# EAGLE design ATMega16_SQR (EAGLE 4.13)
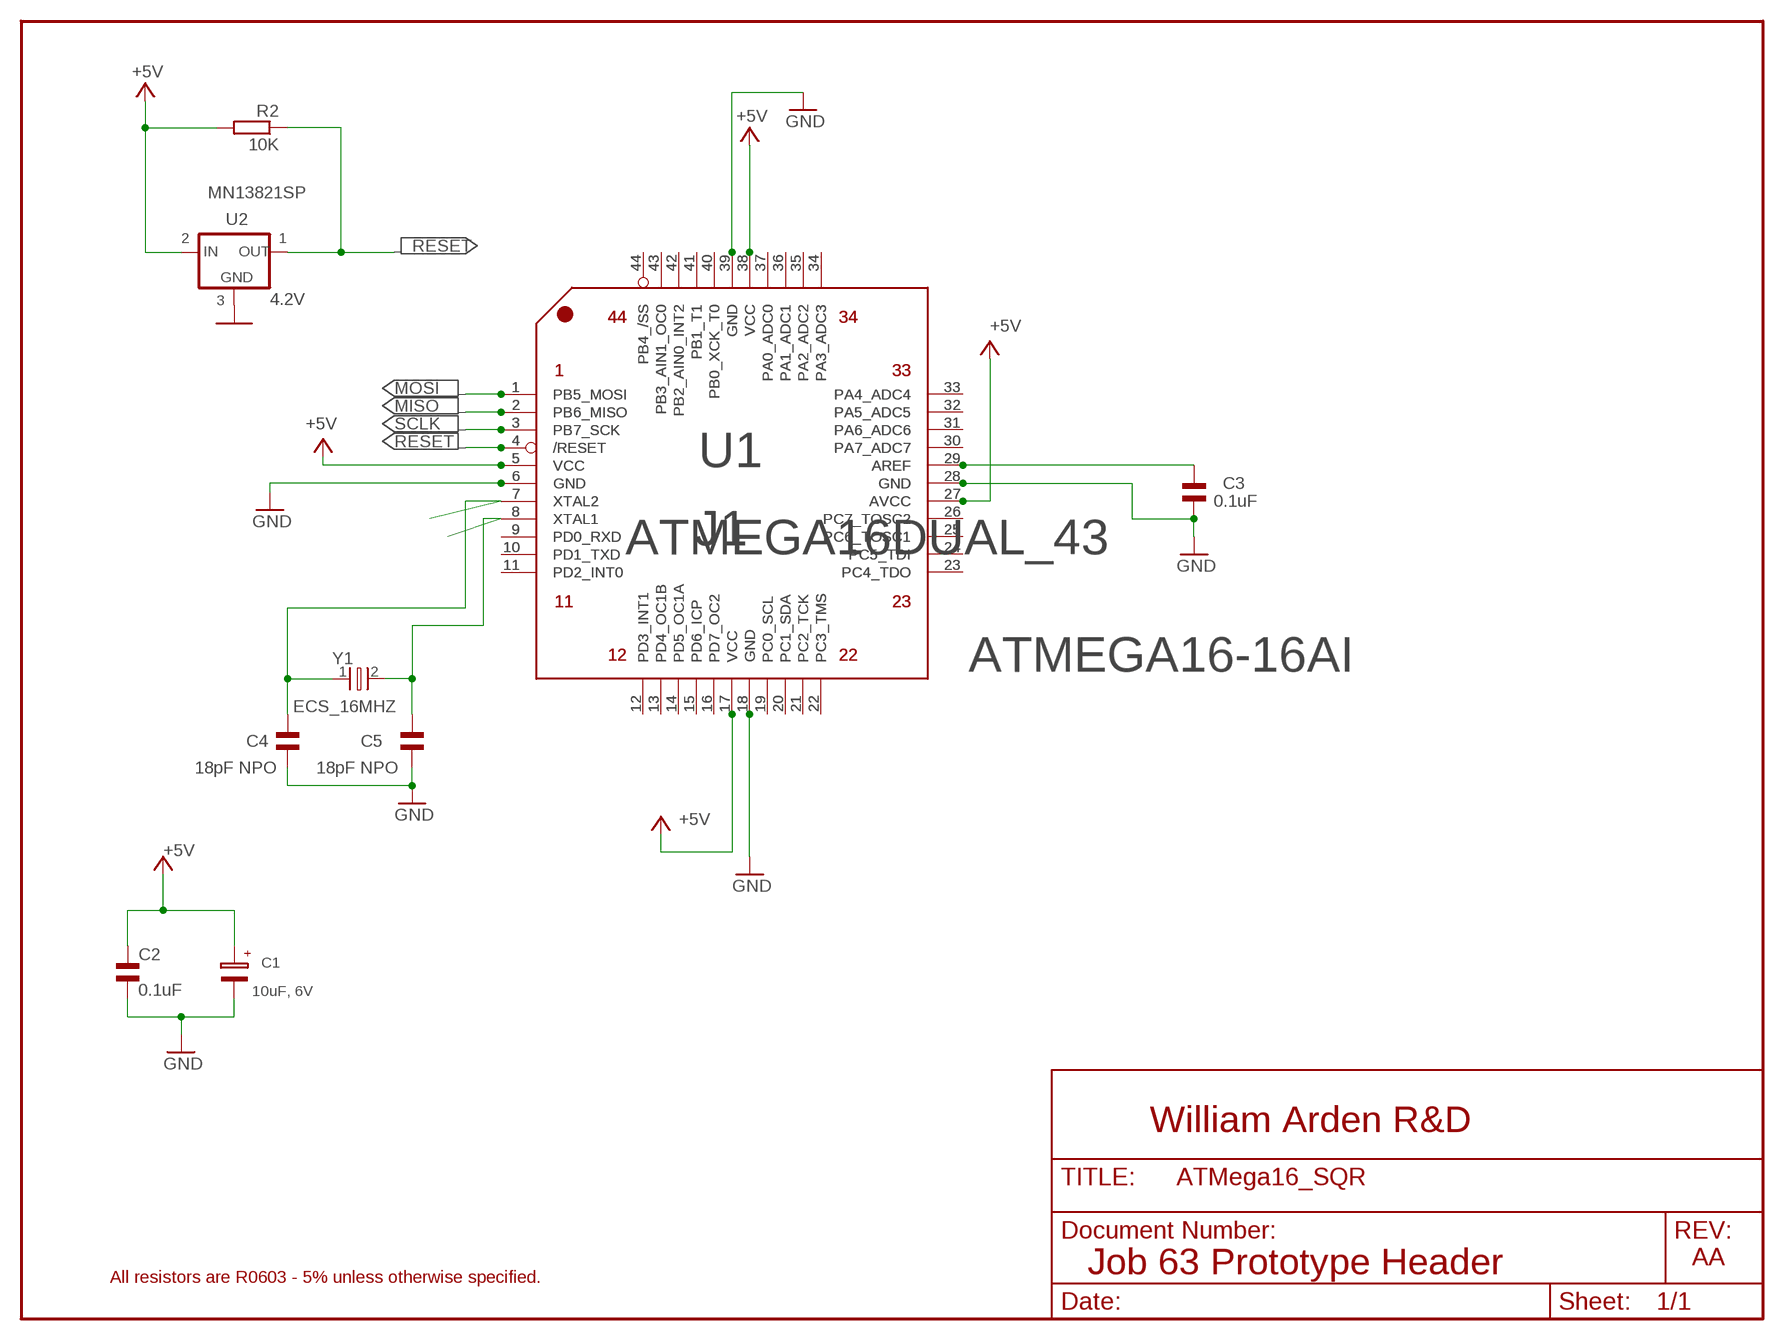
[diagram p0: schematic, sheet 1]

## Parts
C1  10uF, 6V  CAP_TANT_SIZE_A  [CAP_SIZE_A]
C2  0.1uF  C0603  [C0603]
C3  0.1uF  C0603  [C0603]
C4  18pF NPO  C0603  [C0603]
C5  18pF NPO  C0603  [C0603]
J1  ATMEGA16DUAL_43  [HEADER_DUALSQR44_43]
R2  10K  R0603  [R0603]
U1  ATMEGA16-16AI  [TQFP-44]
U2  MN13821SP  MN13821SP_BIGGER_PADS  [MINITYPE_BIGGER_PADS]
Y1  ECS_16MHZ  XTALECS_8MHZ  [XTAL-ECS]

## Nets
+5V: C1.+ C2.2 J1.5(VCC) J1.17(VCC) J1.27(AVCC) J1.38(VCC) R2.2 U1.5(VCC) U1.17(VCC) U1.27(AVCC) U1.38(VCC) U2.2(IN)
ADC0: J1.37(PA0_ADC0) U1.37(PA0_ADC0)
ADC1: J1.36(PA1_ADC1) U1.36(PA1_ADC1)
ADC2: J1.35(PA2_ADC2) U1.35(PA2_ADC2)
ADC3: J1.34(PA3_ADC3) U1.34(PA3_ADC3)
ADC6: J1.31(PA6_ADC6) U1.31(PA6_ADC6)
ADC7: J1.30(PA7_ADC7) U1.30(PA7_ADC7)
AIN0: J1.42(PB2_AIN0_INT2) U1.42(PB2_AIN0_INT2)
AIN1: J1.43(PB3_AIN1_OC0) U1.43(PB3_AIN1_OC0)
GND: C1.- C2.1 C3.1 C4.1 C5.1 J1.6(GND) J1.18(GND) J1.28(GND) J1.39(GND) U1.6(GND) U1.18(GND) U1.28(GND) U1.39(GND) U2.3(GND)
INT0: J1.11(PD2_INT0) U1.11(PD2_INT0)
INT1: J1.12(PD3_INT1) U1.12(PD3_INT1)
LED2: J1.40(PB0_XCK_T0) U1.40(PB0_XCK_T0)
MISO: J1.2(PB6_MISO) U1.2(PB6_MISO)
MOSI: J1.1(PB5_MOSI) U1.1(PB5_MOSI)
N$1: J1.15(PD6_ICP) U1.15(PD6_ICP)
N$2: J1.16(PD7_OC2) U1.16(PD7_OC2)
N$19: C3.2 J1.29(AREF) U1.29(AREF)
NETIN: J1.14(PD5_OC1A) U1.14(PD5_OC1A)
NOTUSED1: J1.7(XTAL2)
NOTUSED2: J1.8(XTAL1)
OC1B: J1.13(PD4_OC1B) U1.13(PD4_OC1B)
PC0: J1.19(PC0_SCL) U1.19(PC0_SCL)
PC1: J1.20(PC1_SDA) U1.20(PC1_SDA)
PC2: J1.21(PC2_TCK) U1.21(PC2_TCK)
PC3: J1.22(PC3_TMS) U1.22(PC3_TMS)
PC4: J1.23(PC4_TDO) U1.23(PC4_TDO)
PC5: J1.24(PC5_TDI) U1.24(PC5_TDI)
PC6: J1.25(PC6_TOSC1) U1.25(PC6_TOSC1)
PC7: J1.26(PC7_TOSC2) U1.26(PC7_TOSC2)
PD0RX: J1.9(PD0_RXD) U1.9(PD0_RXD)
PD1TX: J1.10(PD1_TXD) U1.10(PD1_TXD)
RESET: J1.4(/RESET) R2.1 U1.4(/RESET) U2.1(OUT)
SCLK: J1.3(PB7_SCK) U1.3(PB7_SCK)
SS: J1.44(PB4_/SS) U1.44(PB4_/SS)
T1: J1.41(PB1_T1) U1.41(PB1_T1)
XTAL1: C5.2 U1.8(XTAL1) Y1.2
XTAL2: C4.2 U1.7(XTAL2) Y1.1
YSIG: J1.33(PA4_ADC4) U1.33(PA4_ADC4)
ZSIG: J1.32(PA5_ADC5) U1.32(PA5_ADC5)

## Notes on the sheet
- 4.2V
- William Arden R&D
- AA
- Job 63 Prototype Header
- All resistors are R0603 - 5% unless otherwise specified.

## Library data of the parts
C1 = 0_Darren:CAP_TANT: Capacitor, Tantalum
C2-C5 = ipc-rcl:C0603
J1 U1 = Atmel_Prototype_Header:ATMEGA16: 8-bit AVR Microcontroller with 16K Bytes In-System Programmable Flash
R2 = ipc-rcl:R0603
U2 = 0_Darren:MN13821SP: IC VOLT DETECT 4.2V N-CH OD SMD
Y1 = 0_Darren:XTAL: CRYSTAL 8.00MHZ 18PF SMD , Example: ECS, Inc. Part # ECS-80-18-5P-TR

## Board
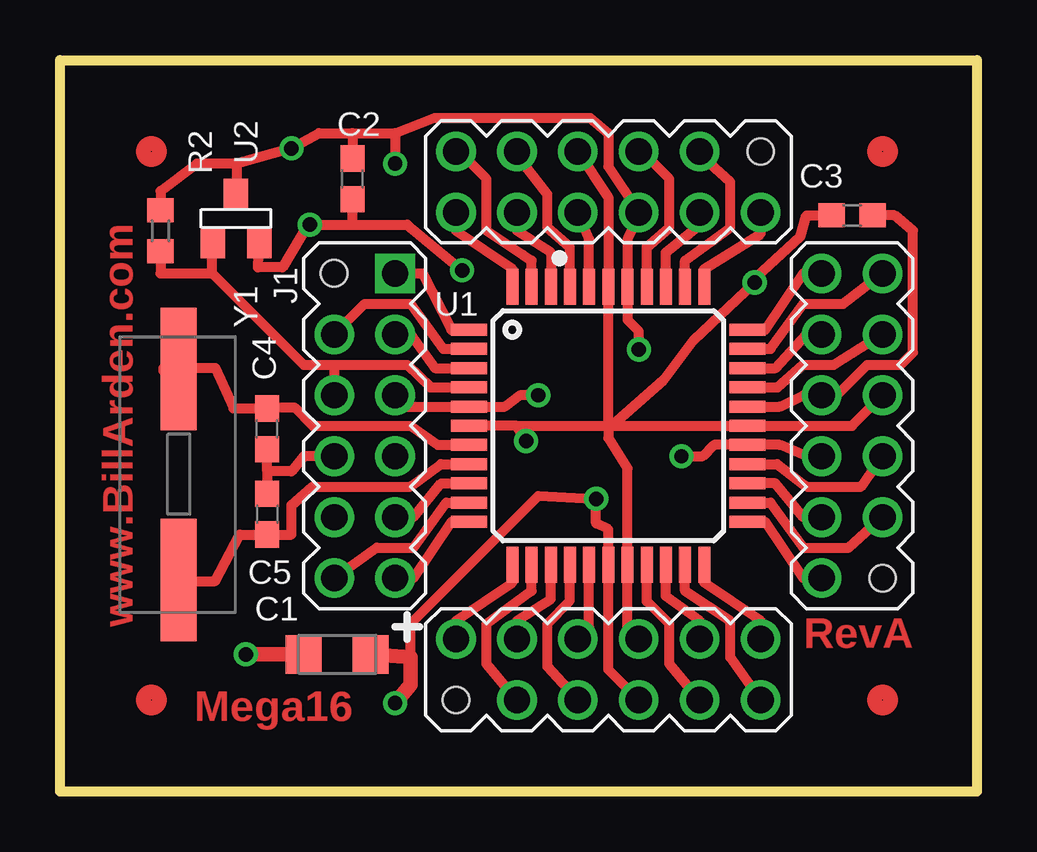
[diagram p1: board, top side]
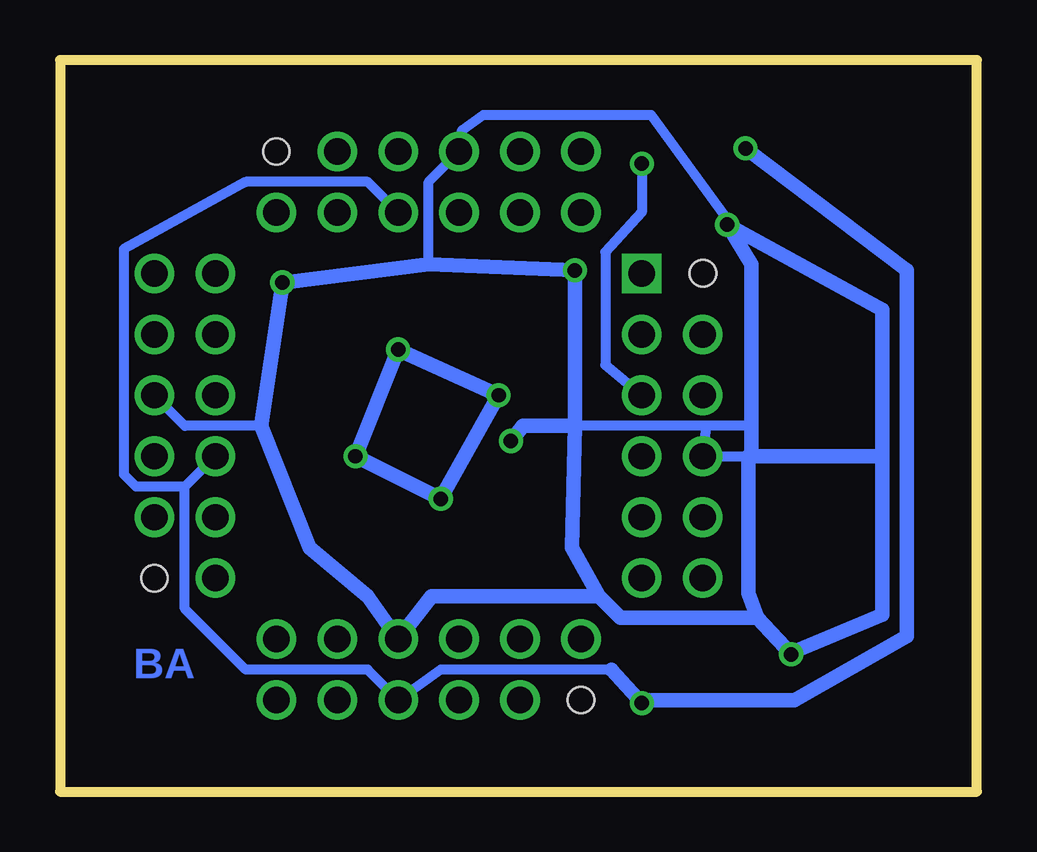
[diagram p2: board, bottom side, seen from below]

Size 38.23 x 30.48 mm. Coordinates in mm from the lower left corner, seen from the top.
Outline: 38.23,30.48 38.23,0 0,0 0,30.48 38.23,30.48
Copper layers (1*16): Top 0.035mm / dielectric 0.5mm / Bottom 0.035mm
Design rules "RestringMinZero": minimum track width 6mil, minimum drill 12mil, track to track 8mil, track to pad 8mil, pad to pad 8mil, via to via 8mil, smd to smd 8mil, copper to edge 0mil, drill to drill 8mil, minimum pad ring 0mil, minimum via ring 8mil, stop-mask expansion 0mil, vias tented up to drill 20mil, thermal gap 12mil
tRestrict: 4 lines

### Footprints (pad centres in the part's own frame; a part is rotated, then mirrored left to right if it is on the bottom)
CAP_SIZE_A = smd 1.5 x 1.6: + -1.4,0; - 1.4,0
C0603 = smd 1.1 x 1: 1 -0.85,0; 2 0.85,0
HEADER_DUALSQR44_43 = drill 1.1 square: 1 -8.89,6.35 | drill 1.1 round: 2 -11.43,3.81; 3 -8.89,3.81; 4 -11.43,1.27; 5 -8.89,1.27; 6 -11.43,-1.27; 7 -8.89,-1.27; 8 -11.43,-3.81; 9 -8.89,-3.81; 10 -11.43,-6.35; 11 -8.89,-6.35; 12 -6.35,-8.89; 13 -3.81,-11.43; 14 -3.81,-8.89; 15 -1.27,-11.43; 16 -1.27,-8.89; 17 1.27,-11.43; 18 1.27,-8.89; 19 3.81,-11.43; 20 3.81,-8.89; 21 6.35,-11.43; 22 6.35,-8.89; 23 8.89,-6.35; 24 11.43,-3.81; 25 8.89,-3.81; 26 11.43,-1.27; 27 8.89,-1.27; 28 11.43,1.27; 29 8.89,1.27; 30 11.43,3.81; 31 8.89,3.81; 32 11.43,6.35; 33 8.89,6.35; 34 6.35,8.89; 35 3.81,11.43; 36 3.81,8.89; 37 1.27,11.43; 38 1.27,8.89; 39 -1.27,11.43; 40 -1.27,8.89; 41 -3.81,11.43; 42 -3.81,8.89; 43 -6.35,11.43; 44 -6.35,8.89 | hole 1.1: -11.43,6.35; -6.35,-11.43; 11.43,-6.35; 6.35,11.43
R0603 = smd 1 x 1.1: 1 -0.85,0; 2 0.85,0
TQFP-44 = smd 1.5 x 0.5: 1 -5.8,4; 2 -5.8,3.2; 3 -5.8,2.4; 4 -5.8,1.6; 5 -5.8,0.8; 6 -5.8,0; 7 -5.8,-0.8; 8 -5.8,-1.6; 9 -5.8,-2.4; 10 -5.8,-3.2; 11 -5.8,-4; 23 5.8,-4; 24 5.8,-3.2; 25 5.8,-2.4; 26 5.8,-1.6; 27 5.8,-0.8; 28 5.8,0; 29 5.8,0.8; 30 5.8,1.6; 31 5.8,2.4; 32 5.8,3.2; 33 5.8,4 | smd 0.5 x 1.5: 12 -4,-5.8; 13 -3.2,-5.8; 14 -2.4,-5.8; 15 -1.6,-5.8; 16 -0.8,-5.8; 17 0,-5.8; 18 0.8,-5.8; 19 1.6,-5.8; 20 2.4,-5.8; 21 3.2,-5.8; 22 4,-5.8; 34 4,5.8; 35 3.2,5.8; 36 2.4,5.8; 37 1.6,5.8; 38 0.8,5.8; 39 0,5.8; 40 -0.8,5.8; 41 -1.6,5.8; 42 -2.4,5.8; 43 -3.2,5.8; 44 -4,5.8
MINITYPE_BIGGER_PADS = smd 1.016 x 1.27: 1 0.991,1.016; 2 0.025,-1.016; 3 -0.94,1.016
XTAL-ECS = smd 5.1 x 1.5: 1 -4.4,0; 2 4.4,0

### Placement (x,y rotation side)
C1  11.56,5.71 180 top
C2  12.19,25.53 90 top
C3  33.02,24 0 top
C4  8.64,15.11 90 top
C5  8.64,11.56 270 top
J1  22.86,15.24 0 top
R2  4.19,23.37 90 top
U1  22.86,15.24 0 top
U2  7.37,23.88 180 top
U$1  [DRAWING]  not placed on the board
U$2  [FIDUCIAL]  3.81,3.81 0 top
U$3  [FIDUCIAL]  34.29,3.81 0 top
U$4  [FIDUCIAL]  34.29,26.67 0 top
U$10  [FIDUCIAL]  3.81,26.67 270 top
Y1  4.95,13.21 270 top

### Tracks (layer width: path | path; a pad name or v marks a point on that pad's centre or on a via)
+5V  (via drill 0.6)
  Top 0.406: J1.5 14.44,16.04 U1.5 18.54,16.04 19.18,16.51 v19.94,16.51 | J1.27 31.11,13.97 30.01,14.44 U1.27 27.27,14.44 26.8,13.97 v25.91,13.97 | J1.17 22.86,5.08 U1.17 22.86,10.92 22.35,11.18 v22.35,12.19 | R2.2 4.19,25.02 5.71,26.16 7.37,26.16 | U2.2 7.37,25.65 7.37,26.16 | v24.13,18.41 24.13,19.18 23.66,19.65 U1.38 23.66,23.02 24.13,24 J1.38 22.86,26.04 22.86,27.43 22.1,28.07 15.62,28.07 13.97,27.43 | 12.19,27.43 C2.2 | 13.97,27.43 v13.97,26.16 | 7.37,26.16 v9.65,26.8 10.79,27.43 12.19,27.43 | 12.19,27.43 13.97,27.43 | 14.61,5.59 14.61,6.99 19.94,12.32 22.23,12.19
  Top 0.61: v9.65,26.8 9.53,26.8 | v13.97,3.68 14.61,4.45 14.61,5.59 C1.+
  Bottom 0.406: 15.24,5.08 22.35,5.08 J1.17 25.4,5.08 30.48,5.08 33.02,7.62 33.02,12.7 | v13.97,26.16 13.97,24.13 15.49,22.48 15.49,17.78 J1.5 | 33.02,12.7 35.05,12.7 35.56,13.21 35.56,22.61 30.48,25.4 25.4,25.4 J1.38 | 33.02,12.7 J1.27 | 13.97,3.81 v13.97,3.68
  Bottom 0.61: v13.97,3.68 15.24,5.08 | 13.97,3.81 7.62,3.81 2.92,6.48 2.92,21.72 v9.65,26.8 | v19.94,16.51 v24.13,18.41 v25.91,13.97 v22.35,12.19 v19.94,16.51
ADC0
  Top 0.406: U1.37 24.46,22.68 25.4,23.5 25.4,25.53 24.26,26.67 J1.37
ADC1
  Top 0.406: U1.36 25.26,22.47 26.67,23.62 J1.36
ADC2
  Top 0.406: U1.35 26.06,22.12 27.94,23.5 27.94,25.4 26.67,26.54 J1.35
ADC3
  Top 0.406: U1.34 26.86,21.78 29.21,23.24 J1.34
ADC6
  Top 0.406: U1.31 29.83,17.64 31.11,19.05 J1.31
ADC7
  Top 0.406: U1.30 29.92,16.84 30.99,17.78 32.26,17.78 J1.30
AIN0
  Top 0.406: U1.42 20.46,22.47 19.05,23.37 J1.42
AIN1
  Top 0.406: U1.43 19.66,22.12 19.3,22.35 17.78,23.37 17.78,25.53 16.51,26.8 J1.43
GND  (via drill 0.6)
  Top 0.406: 22.86,21.59 U1.39 | 22.86,21.59 22.86,24.77 J1.39 | J1.28 33.02,15.24 U1.28 22.86,15.24 | J1.18 23.66,6.82 U1.18 23.66,13.46 22.86,14.73 22.86,15.11 | 22.86,15.11 22.86,21.59 | 19.05,15.24 22.86,15.24 | 22.86,15.24 22.86,15.11 | 8.64,13.34 C4.1 | 8.64,13.34 9.65,13.34 10.16,13.97 J1.6 | 8.64,13.34 C5.1 | U2.3 8.26,21.84 9.27,21.84 10.41,23.75 v10.41,23.62 12.19,23.62 | 19.05,15.24 U1.6 | v19.43,14.61 19.05,15.24 | C3.1 31.11,24 30.86,23.11 29.08,21.46 29.21,21.59 v28.96,21.21 26.42,18.8 25.15,17.14 22.86,15.11 | v16.76,21.72 14.48,23.62 12.19,23.62 | 12.19,23.62 C2.1
  Top 0.61: v7.75,5.71 C1.-
  Bottom 0.406: 9.53,13.97 J1.6 11.3,15.24 | 11.3,15.24 16.76,15.24 | 9.4,15.24 11.3,15.24 | 10.16,23.5 13.59,28.19 20.57,28.19 21.46,27.56 J1.39 22.86,25.4 22.86,21.97 | 29.84,15.24 33.02,15.24 J1.28
  Bottom 0.61: 9.53,13.97 9.53,8.26 9.14,7.24 | v19.43,14.61 18.92,15.24 16.76,15.24 | 7.87,5.71 3.94,7.37 3.94,13.97 | 3.94,13.97 3.94,20.07 v10.41,23.62 9.4,21.97 9.4,15.24 9.4,13.97 3.94,13.97 | 9.14,7.24 v7.75,5.71 | 9.14,7.24 14.86,7.24 15.75,8.13 | 15.75,8.13 16.89,10.16 16.76,15.24 | 15.75,8.13 22.73,8.13 J1.18 25.4,8.13 27.81,10.16 29.84,15.24 v28.96,21.21 22.86,21.97 v16.76,21.72 16.76,15.24
INT0
  Top 0.406: U1.11 16.32,11.24 14.73,8.89 J1.11
INT1
  Top 0.406: U1.12 18.86,8.7 16.51,7.11 J1.12
LED2
  Top 0.406: U1.40 22.06,23.02 J1.40
MISO
  Top 0.406: U1.2 15.98,18.44 14.61,20.32 12.7,20.32 J1.2
MOSI
  Top 0.406: U1.1 16.32,19.24 15.11,21.59 J1.1
N$1
  Top 0.406: U1.15 21.26,7.95 20.32,6.99 20.32,5.21 J1.15
N$2
  Top 0.406: U1.16 22.06,6.82 J1.16
N$19
  Top 0.406: U1.29 30.01,16.04 30.99,16.51 J1.29 32.38,16.51 33.66,17.78 35.05,17.78 35.56,18.29 35.56,23.37 34.8,24 C3.2
NETIN
  Top 0.406: U1.14 20.46,8.01 19.05,7.11 J1.14
OC1B
  Top 0.406: U1.13 19.66,8.36 17.78,6.99 17.78,5.33 J1.13
PC0
  Top 0.406: U1.19 24.46,7.92 25.4,6.99 25.4,5.33 J1.19
PC1
  Top 0.406: U1.20 25.26,8.14 26.67,7.11 J1.20
PC2
  Top 0.406: U1.21 26.06,8.36 27.94,7.11 27.94,5.59 J1.21
PC3
  Top 0.406: U1.22 26.86,8.7 29.21,7.11 J1.22
PC4
  Top 0.406: U1.23 29.4,11.24 30.99,8.89 J1.23
PC5
  Top 0.406: U1.24 29.62,12.04 30.99,10.16 32.89,10.16 J1.24
PC6
  Top 0.406: U1.25 29.83,12.84 30.99,11.43 J1.25
PC7
  Top 0.406: U1.26 29.9,13.64 31.11,12.7 33.4,12.7 J1.26
PD0RX
  Top 0.406: U1.9 15.89,12.84 14.73,11.43 J1.9
PD1TX
  Top 0.406: U1.10 16.1,12.04 14.73,10.16 13.21,10.16 J1.10
RESET
  Top 0.406: U1.4 15.44,16.84 14.48,17.78 11.43,17.78 | 11.43,17.78 J1.4 | 11.43,17.78 10.16,17.78 6.35,21.59 | U2.1 6.35,22.48 6.35,21.59 | 6.35,21.59 4.19,21.59 R2.1
SCLK
  Top 0.406: U1.3 15.63,17.64 14.61,19.05 J1.3
SS
  Top 0.406: U1.44 18.86,21.78 16.51,23.37 J1.44
T1
  Top 0.406: U1.41 21.26,22.68 20.32,23.5 20.32,24.89 18.92,26.67 J1.41
XTAL1
  Top 0.406: U1.8 15.88,13.64 14.61,12.7 10.54,12.7 9.65,11.94 9.65,10.71 C5.2 7.49,10.71 6.48,8.76 4.45,8.76 4.45,8.81 Y1.2
XTAL2
  Top 0.406: U1.7 15.75,14.44 14.61,15.24 10.54,15.24 9.78,16 8.89,16 C4.2 7.24,15.96 6.48,17.65 4.32,17.65 Y1.1 4.32,17.53
YSIG
  Top 0.406: U1.33 29.4,19.24 30.99,21.59 J1.33
ZSIG
  Top 0.406: U1.32 29.62,18.44 30.99,20.32 32.64,20.32 J1.32

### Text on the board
Top: www.BillArden.com | RevA | Mega16
Bottom: BA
